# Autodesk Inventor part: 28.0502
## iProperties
Created: 2007-06
Part Number: 28.0502
Document SubType Name: Modeling
Designer: Andy Moles
Material: UHMW, White
Density: 0.94 g/cm^3
Mass: 1.76433 g
Surface Area: 20.9273 cm^2
Volume: 1.87694 cm^3
Description: TIMING BELT 16 AT 5
Author: Andy Moles
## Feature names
1. Extrusion1
2. NUMBER OF TEETH [Rectangular Pattern]
